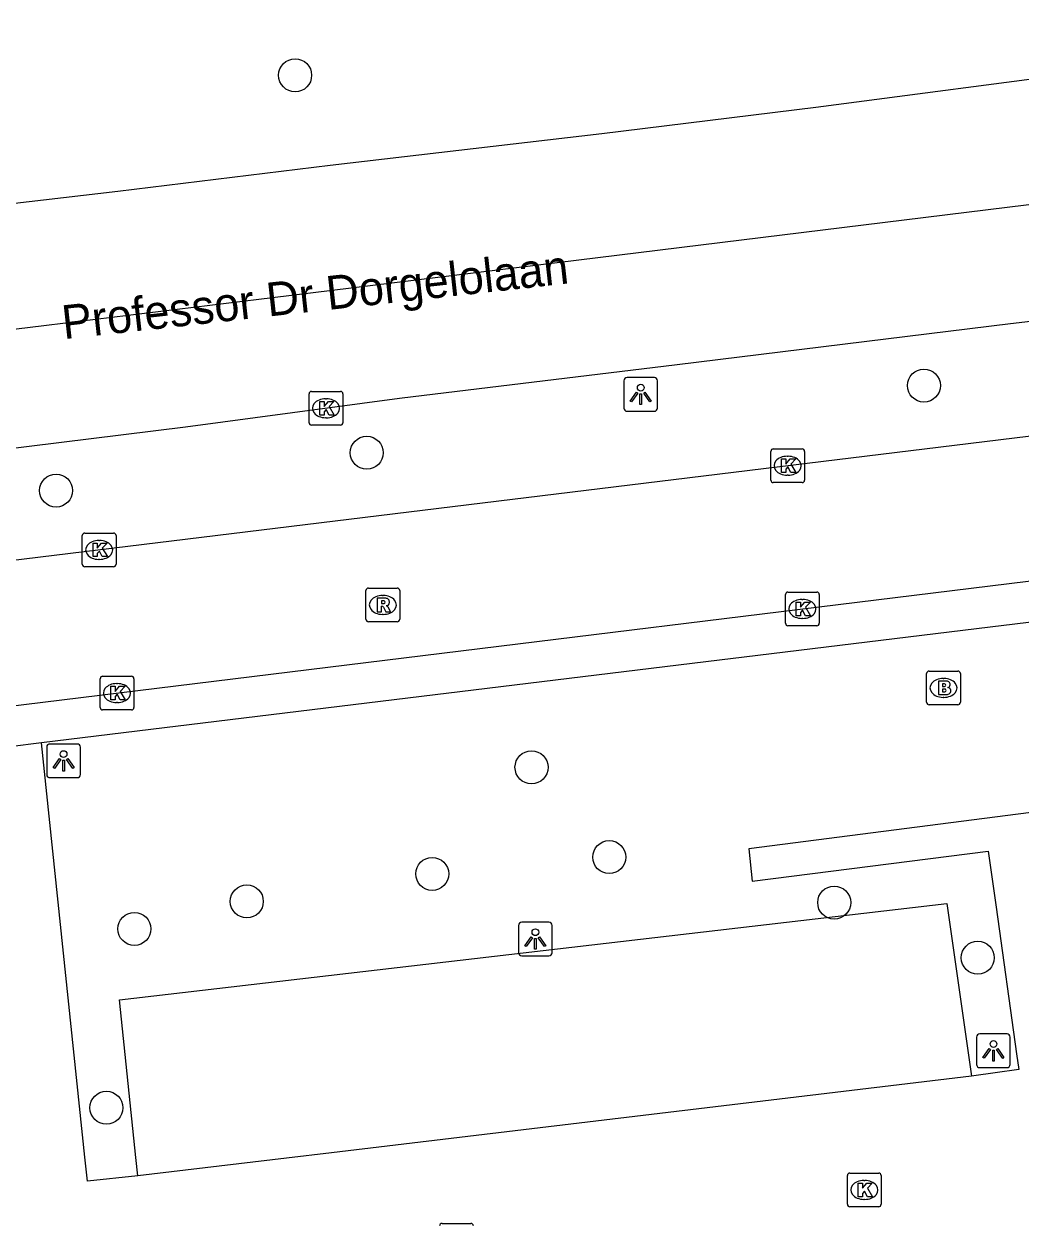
# Model space of a CAD drawing. Extents: x 161477 to 163040, y 383680 to 384868.
# Drawn here: x 161909.43 to 161938.96, y 383998.38 to 384033.98 of the extents above; entities that cross this region are included whole.
import ezdxf

# ---------------------------------------------------------------- set-up
doc = ezdxf.new("R2010")
doc.units = 0
for name, color, linetype in [('IMGEO_Boom', 7, 'Continuous'), ('IMGEO_Brandkraan', 7, 'Continuous'), ('IMGEO_Kolk', 7, 'Continuous'), ('IMGEO_Lichtpunt', 7, 'Continuous'), ('IMGEO_Openbare_ruimte_label', 7, 'Continuous'), ('IMGEO_Parkeervlak_open', 7, 'Continuous'), ('IMGEO_Rijbaan_lokaal_gesloten', 7, 'Continuous'), ('IMGEO_Rijbaan_lokaal_open', 7, 'Continuous'), ('IMGEO_Rioolput', 7, 'Continuous'), ('IMGEO_Voetpad_open', 7, 'Continuous')]:
    doc.layers.add(name, color=color, linetype=linetype)

msp = doc.modelspace()

# ---------------------------------------------------------------- linework, layer by layer
at = {"layer": 'IMGEO_Boom'}
for centre in [(161917.456, 384032.466), (161936.084, 384023.273), (161919.576, 384021.285), (161910.374, 384020.162), (161924.458, 384011.965), (161926.762, 384009.305), (161921.517, 384008.808), (161916.024, 384007.993), (161933.424, 384007.957), (161912.693, 384007.177), (161937.677, 384006.326), (161911.864, 384001.881)]:
    msp.add_circle(centre, 0.489, dxfattribs=at)
at = {"layer": 'IMGEO_Brandkraan'}
for p, q in [((161936.162, 384013.892), (161936.162, 384014.744)), ((161936.237, 384014.818), (161937.089, 384014.818)), ((161936.65, 384014.598), (161936.675, 384014.598)), ((161937.163, 384014.744), (161937.163, 384013.892)), ((161937.089, 384013.818), (161936.237, 384013.818)), ((161936.673, 384014.038), (161936.648, 384014.038))]:
    msp.add_line(p, q, dxfattribs=at)
for points in [[(161936.162, 384013.892), (161936.162, 384014.744)], [(161936.237, 384014.818), (161937.089, 384014.818)], [(161936.51, 384014.518), (161936.51, 384014.118), (161936.723, 384014.118)], [(161936.741, 384014.518), (161936.51, 384014.518)], [(161937.163, 384014.744), (161937.163, 384013.892)], [(161936.689, 384014.437), (161936.635, 384014.437), (161936.635, 384014.361)], [(161936.635, 384014.361), (161936.688, 384014.361)], [(161936.697, 384014.285), (161936.635, 384014.285), (161936.635, 384014.204)], [(161936.635, 384014.204), (161936.697, 384014.204)], [(161937.089, 384013.818), (161936.237, 384013.818)]]:
    msp.add_lwpolyline(points, dxfattribs=at)
for centre, radius, start, end in [((161936.239, 384014.742), 0.0765, 91.552, 178.448), ((161936.239, 384014.742), 0.0765, 91.552, 178.448), ((161936.745, 384014.373), 0.145, 59.4692, 91.5367), ((161936.77, 384014.42), 0.0922, 285.5137, 58.1501), ((161937.087, 384014.742), 0.0765, 1.552, 88.448), ((161937.087, 384014.742), 0.0765, 1.552, 88.448), ((161936.69, 384014.399), 0.0379, 267.8285, 90.9355), ((161936.698, 384014.244), 0.0404, 269.8759, 90.5077), ((161936.729, 384014.369), 0.251, 268.6676, 293.5347), ((161936.775, 384014.228), 0.105, 301.3115, 78.989), ((161936.239, 384013.894), 0.0765, 181.552, 268.448), ((161936.239, 384013.894), 0.0765, 181.552, 268.448), ((161937.087, 384013.894), 0.0765, 271.552, 358.448), ((161937.087, 384013.894), 0.0765, 271.552, 358.448)]:
    msp.add_arc(centre, radius, start, end, dxfattribs=at)
for centre, major_axis, ratio, start_param, end_param in [((161936.649, 384014.318), (-0.387, 0.002), 0.722429, 4.712389, 7.853982), ((161936.674, 384014.318), (-0.39, 0.002), 0.717154, 1.570796, 4.712389)]:
    msp.add_ellipse(centre, major_axis=major_axis, ratio=ratio, start_param=start_param, end_param=end_param, dxfattribs=at)
at = {"layer": 'IMGEO_Kolk'}
for p, q in [((161917.944, 384023.101), (161918.796, 384023.101)), ((161917.869, 384022.175), (161917.869, 384023.027)), ((161918.357, 384022.881), (161918.382, 384022.881)), ((161918.87, 384023.027), (161918.87, 384022.175)), ((161918.796, 384022.101), (161917.944, 384022.101)), ((161918.38, 384022.321), (161918.355, 384022.321)), ((161931.546, 384020.474), (161931.546, 384021.326)), ((161931.621, 384021.4), (161932.473, 384021.4)), ((161932.547, 384021.326), (161932.547, 384020.474)), ((161932.034, 384021.18), (161932.059, 384021.18)), ((161932.057, 384020.62), (161932.032, 384020.62)), ((161932.473, 384020.4), (161931.621, 384020.4)), ((161911.15, 384017.98), (161911.15, 384018.832)), ((161911.225, 384018.906), (161912.077, 384018.906)), ((161912.151, 384018.832), (161912.151, 384017.98)), ((161911.638, 384018.686), (161911.663, 384018.686)), ((161911.661, 384018.126), (161911.636, 384018.126)), ((161912.077, 384017.906), (161911.225, 384017.906)), ((161931.98, 384016.231), (161931.98, 384017.083)), ((161932.055, 384017.157), (161932.907, 384017.157)), ((161932.981, 384017.083), (161932.981, 384016.231)), ((161932.468, 384016.937), (161932.493, 384016.937)), ((161932.491, 384016.377), (161932.466, 384016.377)), ((161932.907, 384016.157), (161932.055, 384016.157)), ((161911.679, 384013.739), (161911.679, 384014.591)), ((161911.754, 384014.665), (161912.606, 384014.665)), ((161912.68, 384014.591), (161912.68, 384013.739)), ((161912.167, 384014.445), (161912.192, 384014.445)), ((161912.19, 384013.885), (161912.165, 384013.885)), ((161912.606, 384013.665), (161911.754, 384013.665)), ((161933.89, 383999.945), (161934.742, 383999.945)), ((161933.815, 383999.019), (161933.815, 383999.871)), ((161934.303, 383999.725), (161934.328, 383999.725)), ((161934.816, 383999.871), (161934.816, 383999.019)), ((161934.742, 383998.945), (161933.89, 383998.945)), ((161934.326, 383999.165), (161934.301, 383999.165)), ((161921.809, 383998.452), (161922.661, 383998.452))]:
    msp.add_line(p, q, dxfattribs=at)
for points in [[(161917.944, 384023.101), (161918.796, 384023.101)], [(161917.869, 384022.175), (161917.869, 384023.027)], [(161918.19, 384022.801), (161918.313, 384022.801), (161918.313, 384022.65), (161918.443, 384022.801), (161918.607, 384022.801), (161918.461, 384022.65), (161918.614, 384022.401), (161918.462, 384022.401), (161918.377, 384022.565), (161918.313, 384022.498), (161918.313, 384022.401), (161918.19, 384022.401), (161918.19, 384022.801)], [(161918.87, 384023.027), (161918.87, 384022.175)], [(161918.796, 384022.101), (161917.944, 384022.101)], [(161931.546, 384020.474), (161931.546, 384021.326)], [(161931.621, 384021.4), (161932.473, 384021.4)], [(161932.547, 384021.326), (161932.547, 384020.474)], [(161931.867, 384021.1), (161931.99, 384021.1), (161931.99, 384020.949), (161932.12, 384021.1), (161932.284, 384021.1), (161932.138, 384020.949), (161932.291, 384020.7), (161932.139, 384020.7), (161932.054, 384020.864), (161931.99, 384020.797), (161931.99, 384020.7), (161931.867, 384020.7), (161931.867, 384021.1)], [(161932.473, 384020.4), (161931.621, 384020.4)], [(161911.15, 384017.98), (161911.15, 384018.832)], [(161911.225, 384018.906), (161912.077, 384018.906)], [(161912.151, 384018.832), (161912.151, 384017.98)], [(161911.471, 384018.606), (161911.594, 384018.606), (161911.594, 384018.455), (161911.724, 384018.606), (161911.888, 384018.606), (161911.742, 384018.455), (161911.895, 384018.206), (161911.743, 384018.206), (161911.658, 384018.37), (161911.594, 384018.303), (161911.594, 384018.206), (161911.471, 384018.206), (161911.471, 384018.606)], [(161912.077, 384017.906), (161911.225, 384017.906)], [(161931.98, 384016.231), (161931.98, 384017.083)], [(161932.055, 384017.157), (161932.907, 384017.157)], [(161932.981, 384017.083), (161932.981, 384016.231)], [(161932.301, 384016.857), (161932.424, 384016.857), (161932.424, 384016.706), (161932.554, 384016.857), (161932.718, 384016.857), (161932.572, 384016.706), (161932.725, 384016.457), (161932.573, 384016.457), (161932.488, 384016.621), (161932.424, 384016.554), (161932.424, 384016.457), (161932.301, 384016.457), (161932.301, 384016.857)], [(161932.907, 384016.157), (161932.055, 384016.157)], [(161911.679, 384013.739), (161911.679, 384014.591)], [(161911.754, 384014.665), (161912.606, 384014.665)], [(161912.68, 384014.591), (161912.68, 384013.739)], [(161912, 384014.365), (161912.123, 384014.365), (161912.123, 384014.214), (161912.253, 384014.365), (161912.417, 384014.365), (161912.271, 384014.214), (161912.424, 384013.965), (161912.272, 384013.965), (161912.187, 384014.129), (161912.123, 384014.062), (161912.123, 384013.965), (161912, 384013.965), (161912, 384014.365)], [(161912.606, 384013.665), (161911.754, 384013.665)], [(161933.89, 383999.945), (161934.742, 383999.945)], [(161933.815, 383999.019), (161933.815, 383999.871)], [(161934.136, 383999.645), (161934.259, 383999.645), (161934.259, 383999.494), (161934.389, 383999.645), (161934.553, 383999.645), (161934.407, 383999.494), (161934.56, 383999.245), (161934.408, 383999.245), (161934.323, 383999.409), (161934.259, 383999.342), (161934.259, 383999.245), (161934.136, 383999.245), (161934.136, 383999.645)], [(161934.816, 383999.871), (161934.816, 383999.019)], [(161934.742, 383998.945), (161933.89, 383998.945)], [(161921.809, 383998.452), (161922.661, 383998.452)]]:
    msp.add_lwpolyline(points, dxfattribs=at)
for centre, start, end in [((161917.946, 384023.025), 91.552, 178.448), ((161917.946, 384023.025), 91.552, 178.448), ((161918.794, 384023.025), 1.552, 88.448), ((161918.794, 384023.025), 1.552, 88.448), ((161917.946, 384022.177), 181.552, 268.448), ((161917.946, 384022.177), 181.552, 268.448), ((161918.794, 384022.177), 271.552, 358.448), ((161918.794, 384022.177), 271.552, 358.448), ((161931.623, 384021.324), 91.552, 178.448), ((161931.623, 384021.324), 91.552, 178.448), ((161932.471, 384021.324), 1.552, 88.448), ((161932.471, 384021.324), 1.552, 88.448), ((161931.623, 384020.476), 181.552, 268.448), ((161931.623, 384020.476), 181.552, 268.448), ((161932.471, 384020.476), 271.552, 358.448), ((161932.471, 384020.476), 271.552, 358.448), ((161911.227, 384018.83), 91.552, 178.448), ((161911.227, 384018.83), 91.552, 178.448), ((161912.075, 384018.83), 1.552, 88.448), ((161912.075, 384018.83), 1.552, 88.448), ((161911.227, 384017.982), 181.552, 268.448), ((161911.227, 384017.982), 181.552, 268.448), ((161912.075, 384017.982), 271.552, 358.448), ((161912.075, 384017.982), 271.552, 358.448), ((161932.057, 384017.081), 91.552, 178.448), ((161932.057, 384017.081), 91.552, 178.448), ((161932.905, 384017.081), 1.552, 88.448), ((161932.905, 384017.081), 1.552, 88.448), ((161932.057, 384016.233), 181.552, 268.448), ((161932.057, 384016.233), 181.552, 268.448), ((161932.905, 384016.233), 271.552, 358.448), ((161932.905, 384016.233), 271.552, 358.448), ((161911.756, 384014.589), 91.552, 178.448), ((161911.756, 384014.589), 91.552, 178.448), ((161912.604, 384014.589), 1.552, 88.448), ((161912.604, 384014.589), 1.552, 88.448), ((161911.756, 384013.741), 181.552, 268.448), ((161911.756, 384013.741), 181.552, 268.448), ((161912.604, 384013.741), 271.552, 358.448), ((161912.604, 384013.741), 271.552, 358.448), ((161933.892, 383999.869), 91.552, 178.448), ((161933.892, 383999.869), 91.552, 178.448), ((161934.74, 383999.869), 1.552, 88.448), ((161934.74, 383999.869), 1.552, 88.448), ((161933.892, 383999.021), 181.552, 268.448), ((161933.892, 383999.021), 181.552, 268.448), ((161934.74, 383999.021), 271.552, 358.448), ((161934.74, 383999.021), 271.552, 358.448), ((161921.811, 383998.376), 91.552, 178.448), ((161921.811, 383998.376), 91.552, 178.448), ((161922.659, 383998.376), 1.552, 88.448), ((161922.659, 383998.376), 1.552, 88.448)]:
    msp.add_arc(centre, 0.0765, start, end, dxfattribs=at)
for centre, major_axis, ratio, start_param, end_param in [((161918.356, 384022.601), (-0.387, 0.002), 0.722429, 4.712389, 7.853982), ((161918.381, 384022.601), (-0.39, 0.002), 0.717154, 1.570796, 4.712389), ((161932.033, 384020.9), (-0.387, 0.002), 0.722429, 4.712389, 7.853982), ((161932.058, 384020.9), (-0.39, 0.002), 0.717154, 1.570796, 4.712389), ((161911.637, 384018.406), (-0.387, 0.002), 0.722429, 4.712389, 7.853982), ((161911.662, 384018.406), (-0.39, 0.002), 0.717154, 1.570796, 4.712389), ((161932.467, 384016.657), (-0.387, 0.002), 0.722429, 4.712389, 7.853982), ((161932.492, 384016.657), (-0.39, 0.002), 0.717154, 1.570796, 4.712389), ((161912.166, 384014.165), (-0.387, 0.002), 0.722429, 4.712389, 7.853982), ((161912.191, 384014.165), (-0.39, 0.002), 0.717154, 1.570796, 4.712389), ((161934.302, 383999.445), (-0.387, 0.002), 0.722429, 4.712389, 7.853982), ((161934.327, 383999.445), (-0.39, 0.002), 0.717154, 1.570796, 4.712389)]:
    msp.add_ellipse(centre, major_axis=major_axis, ratio=ratio, start_param=start_param, end_param=end_param, dxfattribs=at)
at = {"layer": 'IMGEO_Lichtpunt'}
for p, q in [((161927.195, 384023.415), (161927.195, 384022.608)), ((161927.195, 384023.415), (161927.195, 384022.608)), ((161928.097, 384023.51), (161927.289, 384023.51)), ((161928.097, 384023.51), (161927.289, 384023.51)), ((161928.191, 384022.608), (161928.191, 384023.415)), ((161928.191, 384022.608), (161928.191, 384023.415)), ((161927.289, 384022.514), (161928.097, 384022.514)), ((161927.289, 384022.514), (161928.097, 384022.514)), ((161910.098, 384012.561), (161910.098, 384011.754)), ((161910.098, 384012.561), (161910.098, 384011.754)), ((161911, 384012.656), (161910.192, 384012.656)), ((161911, 384012.656), (161910.192, 384012.656)), ((161911.094, 384011.754), (161911.094, 384012.561)), ((161911.094, 384011.754), (161911.094, 384012.561)), ((161910.192, 384011.66), (161911, 384011.66)), ((161910.192, 384011.66), (161911, 384011.66)), ((161924.975, 384007.375), (161924.167, 384007.375)), ((161924.975, 384007.375), (161924.167, 384007.375)), ((161924.073, 384007.28), (161924.073, 384006.473)), ((161924.073, 384007.28), (161924.073, 384006.473)), ((161925.069, 384006.473), (161925.069, 384007.28)), ((161925.069, 384006.473), (161925.069, 384007.28)), ((161924.167, 384006.379), (161924.975, 384006.379)), ((161924.167, 384006.379), (161924.975, 384006.379)), ((161937.643, 384003.971), (161937.643, 384003.164)), ((161937.643, 384003.971), (161937.643, 384003.164)), ((161938.545, 384004.066), (161937.737, 384004.066)), ((161938.545, 384004.066), (161937.737, 384004.066)), ((161938.639, 384003.164), (161938.639, 384003.971)), ((161938.639, 384003.164), (161938.639, 384003.971)), ((161937.737, 384003.07), (161938.545, 384003.07)), ((161937.737, 384003.07), (161938.545, 384003.07))]:
    msp.add_line(p, q, dxfattribs=at)
for points in [[(161927.569, 384023.079), (161927.608, 384023.051), (161927.42, 384022.789), (161927.382, 384022.816), (161927.569, 384023.079)], [(161927.781, 384023.051), (161927.819, 384023.078), (161928.006, 384022.816), (161927.967, 384022.788), (161927.781, 384023.051)], [(161927.671, 384023.031), (161927.718, 384023.031), (161927.718, 384022.709), (161927.671, 384022.709), (161927.671, 384023.031)], [(161910.472, 384012.225), (161910.511, 384012.197), (161910.323, 384011.935), (161910.285, 384011.962), (161910.472, 384012.225)], [(161910.574, 384012.177), (161910.621, 384012.177), (161910.621, 384011.855), (161910.574, 384011.855), (161910.574, 384012.177)], [(161910.684, 384012.197), (161910.722, 384012.224), (161910.909, 384011.962), (161910.87, 384011.934), (161910.684, 384012.197)], [(161924.447, 384006.944), (161924.486, 384006.916), (161924.298, 384006.654), (161924.26, 384006.681), (161924.447, 384006.944)], [(161924.549, 384006.896), (161924.596, 384006.896), (161924.596, 384006.574), (161924.549, 384006.574), (161924.549, 384006.896)], [(161924.659, 384006.916), (161924.697, 384006.943), (161924.884, 384006.681), (161924.845, 384006.653), (161924.659, 384006.916)], [(161938.017, 384003.635), (161938.056, 384003.607), (161937.868, 384003.345), (161937.83, 384003.372), (161938.017, 384003.635)], [(161938.119, 384003.587), (161938.166, 384003.587), (161938.166, 384003.265), (161938.119, 384003.265), (161938.119, 384003.587)], [(161938.229, 384003.607), (161938.267, 384003.634), (161938.454, 384003.372), (161938.415, 384003.344), (161938.229, 384003.607)]]:
    msp.add_lwpolyline(points, dxfattribs=at)
for centre in [(161927.694, 384023.213), (161910.597, 384012.359), (161924.572, 384007.078), (161938.142, 384003.769)]:
    msp.add_circle(centre, 0.0994, dxfattribs=at)
for centre, start, end in [((161927.289, 384023.415), 90, 180), ((161927.289, 384023.415), 90, 180), ((161928.097, 384023.415), 0, 90), ((161928.097, 384023.415), 0, 90), ((161927.289, 384022.608), 180, 270), ((161927.289, 384022.608), 180, 270), ((161928.097, 384022.608), 270, 0), ((161928.097, 384022.608), 270, 360), ((161910.192, 384012.561), 90, 180), ((161910.192, 384012.561), 90, 180), ((161911, 384012.561), 0, 90), ((161911, 384012.561), 0, 90), ((161910.192, 384011.754), 180, 270), ((161910.192, 384011.754), 180, 270), ((161911, 384011.754), 270, 0), ((161911, 384011.754), 270, 360), ((161924.167, 384007.28), 90, 180), ((161924.167, 384007.28), 90, 180), ((161924.975, 384007.28), 0, 90), ((161924.975, 384007.28), 0, 90), ((161924.167, 384006.473), 180, 270), ((161924.167, 384006.473), 180, 270), ((161924.975, 384006.473), 270, 0), ((161924.975, 384006.473), 270, 360), ((161937.737, 384003.971), 90, 180), ((161937.737, 384003.971), 90, 180), ((161938.545, 384003.971), 0, 90), ((161938.545, 384003.971), 0, 90), ((161937.737, 384003.164), 180, 270), ((161937.737, 384003.164), 180, 270), ((161938.545, 384003.164), 270, 0), ((161938.545, 384003.164), 270, 360)]:
    msp.add_arc(centre, 0.0946, start, end, dxfattribs=at)
at = {"layer": 'IMGEO_Parkeervlak_open'}
msp.add_lwpolyline([(161912.799, 383999.865), (161912.741, 384000.409), (161912.251, 384005.077), (161936.764, 384007.928), (161936.813, 384007.584), (161937.489, 384002.813)], dxfattribs=at)
at = {"layer": 'IMGEO_Rijbaan_lokaal_gesloten'}
for points in [[(161696.618, 383999.076), (161717.081, 384001.544), (161768.879, 384007.897), (161825.477, 384014.75), (161917.35, 384025.954), (162007.495, 384037.033), (162008.923, 384037.209), (162102.422, 384048.613), (162177.172, 384057.667), (162248.391, 384066.39)], [(162036.516, 384037.016), (162009.54, 384033.893), (162008.109, 384033.699), (162000, 384032.599), (161996.88, 384032.194), (161990.538, 384031.465), (161981.752, 384030.422), (161974.434, 384029.511), (161966.996, 384028.578), (161961.213, 384027.84), (161952.768, 384026.784), (161946.406, 384026.014), (161938.648, 384025.104), (161928.777, 384023.886), (161920.55, 384022.895), (161914.21, 384022.046), (161904.857, 384020.891), (161896.801, 384019.864), (161888.804, 384018.877), (161880.897, 384017.893), (161873.318, 384016.997), (161865.049, 384016.046), (161854.527, 384014.894)], [(161955.645, 384034.342), (161947.767, 384033.359), (161941.167, 384032.594), (161932.884, 384031.511), (161926.538, 384030.732), (161918.49, 384029.795), (161912.208, 384029.026), (161904.739, 384028.152), (161898.618, 384027.408), (161892.7, 384026.697), (161887.995, 384026.183), (161881.096, 384025.303), (161875.103, 384024.611), (161868.493, 384023.755), (161862.148, 384023.025), (161854.166, 384022.062), (161823.343, 384018.177), (161748.637, 384009.081), (161744.626, 384008.574)], [(161953.69, 384023.463), (161942.24, 384022.146), (161865.698, 384012.787), (161859.469, 384012.052), (161858.533, 384011.921)], [(161908.859, 384013.757), (161947.609, 384018.515), (161953.587, 384019.102)]]:
    msp.add_lwpolyline(points, dxfattribs=at)
at = {"layer": 'IMGEO_Rijbaan_lokaal_open'}
for points in [[(161942.419, 384016.653), (161943.227, 384010.041), (161941.996, 384009.912), (161941.867, 384010.958), (161930.899, 384009.549), (161930.999, 384008.59), (161937.988, 384009.484), (161938.22, 384007.825), (161938.827, 384003.48), (161938.893, 384003.011), (161938.193, 384002.912), (161937.564, 384002.823), (161937.489, 384002.813)], [(161909.941, 384012.689), (161909.001, 384012.574)], [(161912.799, 383999.865), (161911.306, 383999.708), (161911.231, 384000.416), (161909.941, 384012.689)], [(161937.489, 384002.813), (161918.529, 384000.549), (161917.202, 384000.391), (161912.799, 383999.865)]]:
    msp.add_lwpolyline(points, dxfattribs=at)
at = {"layer": 'IMGEO_Rioolput'}
for p, q in [((161919.553, 384016.35), (161919.553, 384017.202)), ((161919.628, 384017.276), (161920.48, 384017.276)), ((161920.041, 384017.056), (161920.066, 384017.056)), ((161920.554, 384017.202), (161920.554, 384016.35)), ((161920.48, 384016.276), (161919.628, 384016.276)), ((161920.064, 384016.496), (161920.039, 384016.496))]:
    msp.add_line(p, q, dxfattribs=at)
for points in [[(161919.553, 384016.35), (161919.553, 384017.202)], [(161919.628, 384017.276), (161920.48, 384017.276)], [(161920.554, 384017.202), (161920.554, 384016.35)], [(161920.142, 384016.974), (161919.89, 384016.976), (161919.89, 384016.576)], [(161919.89, 384016.576), (161920.014, 384016.576), (161920.014, 384016.738), (161920.025, 384016.738)], [(161920.068, 384016.895), (161920.014, 384016.895), (161920.014, 384016.814)], [(161920.014, 384016.814), (161920.066, 384016.814)], [(161920.072, 384016.709), (161920.143, 384016.576), (161920.283, 384016.576), (161920.218, 384016.702)], [(161920.48, 384016.276), (161919.628, 384016.276)]]:
    msp.add_lwpolyline(points, dxfattribs=at)
for centre, radius, start, end in [((161919.63, 384017.2), 0.0765, 91.552, 178.448), ((161919.63, 384017.2), 0.0765, 91.552, 178.448), ((161920.478, 384017.2), 0.0765, 1.552, 88.448), ((161920.478, 384017.2), 0.0765, 1.552, 88.448), ((161920.024, 384016.685), 0.0533, 26.0293, 88.6989), ((161920.05, 384017.003), 0.19, 274.7715, 282.9687), ((161920.074, 384016.799), 0.0964, 77.0061, 93.1865), ((161920.088, 384016.856), 0.0378, 276.6634, 79.6772), ((161920.141, 384016.864), 0.109, 350.3612, 89.416), ((161920.139, 384016.864), 0.112, 277.5842, 350.9817), ((161920.123, 384016.649), 0.108, 29.5134, 73.7905), ((161919.63, 384016.352), 0.0765, 181.552, 268.448), ((161919.63, 384016.352), 0.0765, 181.552, 268.448), ((161920.478, 384016.352), 0.0765, 271.552, 358.448), ((161920.478, 384016.352), 0.0765, 271.552, 358.448)]:
    msp.add_arc(centre, radius, start, end, dxfattribs=at)
for centre, major_axis, ratio, start_param, end_param in [((161920.04, 384016.776), (-0.387, 0.002), 0.722429, 4.712389, 7.853982), ((161920.065, 384016.776), (-0.39, 0.002), 0.717154, 1.570796, 4.712389)]:
    msp.add_ellipse(centre, major_axis=major_axis, ratio=ratio, start_param=start_param, end_param=end_param, dxfattribs=at)
at = {"layer": 'IMGEO_Voetpad_open'}
msp.add_lwpolyline([(161942.419, 384016.653), (161909.941, 384012.689)], dxfattribs=at)

# ---------------------------------------------------------------- texts
at = {"layer": 'IMGEO_Openbare_ruimte_label'}
msp.add_text('Professor Dr Dorgelolaan', height=1, rotation=6.3149, dxfattribs=at).set_placement((161910.602, 384024.647))

doc.saveas('drawing.dxf')
